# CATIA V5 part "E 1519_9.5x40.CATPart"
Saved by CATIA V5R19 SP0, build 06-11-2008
Part number: E 1519_9.5x40
Definition: E 1519_9.5x40
Nomenclature: E 1519_9.5x40
Source: Unknown
Description: PART--DESC
Bounding box of the stored display mesh (mm): x -5.95 to 5.95, y -6.95 to 6.95, z -80 to -40
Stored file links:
  C:\Users\jsmid\Desktop\DP_Smidak_Forma LEGO\E 1519_9.5x40.CATPart
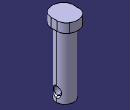
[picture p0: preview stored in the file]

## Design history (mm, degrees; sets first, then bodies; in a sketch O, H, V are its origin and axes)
Body1 "E 1519_9.5x40" (main body)
  Solid1: solid without history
